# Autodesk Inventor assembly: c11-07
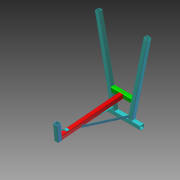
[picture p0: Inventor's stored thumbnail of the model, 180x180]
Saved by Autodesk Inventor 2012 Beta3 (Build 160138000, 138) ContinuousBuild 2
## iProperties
Created: 2011-01
Part Number: c11-07
Document SubType Name: Assembly
Designer: Beta-8540w
_SolveAssemblyDoc: Frame Generator Solve Assembly
_Version: 15.0.0
Author: Beta-8540w
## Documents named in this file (3)
- C:\Inventor 2012 Essentials\Assemblies\Chapter 11\c11-07.iam
- C:\Inventor 2012 Essentials\Parts\Chapter 11\c11-01.ipt
- C:\Inventor 2012 Essentials\Assemblies\Chapter 11\Frame\Frame c11-07.iam
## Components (2 placed, 2 different names)
1. c11-01:1
2. Frame c11-07:1 [sub-assembly]
